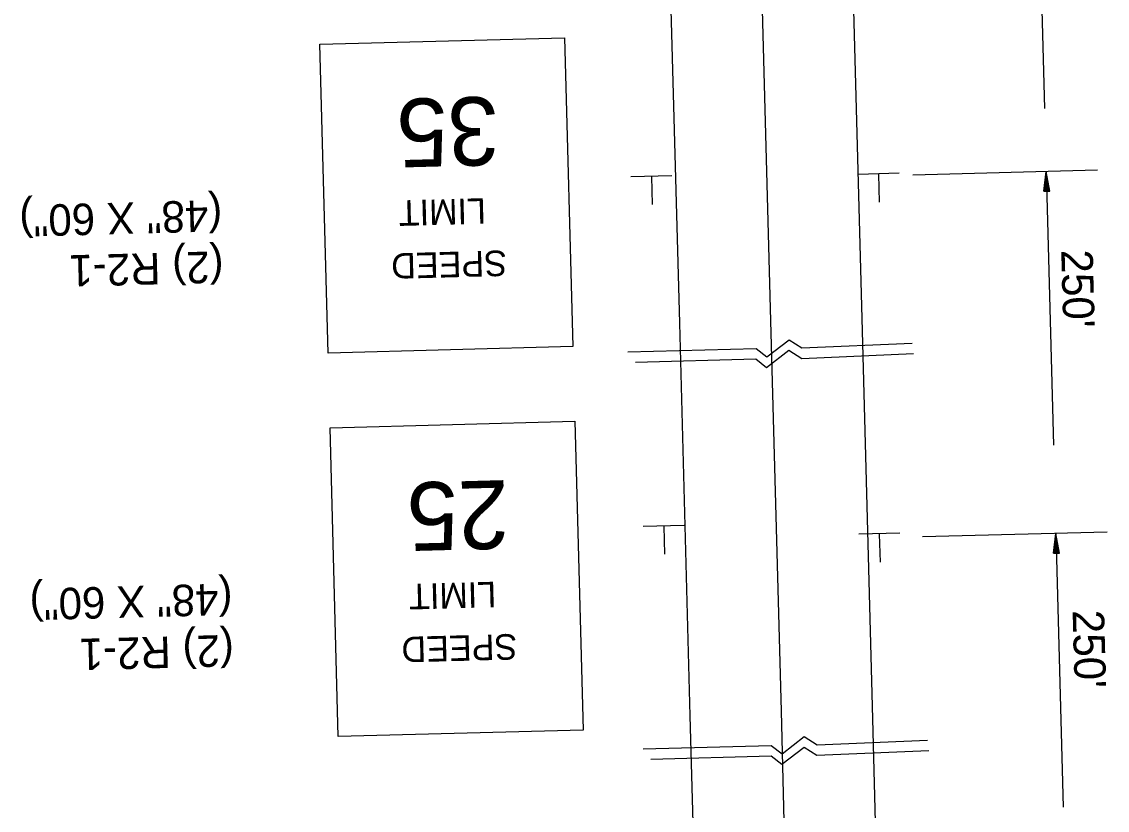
# Model space of a CAD drawing. Extents: x 1929624 to 1932607, y 596315 to 605533.
# Drawn here: x 1930074.1 to 1930285.9, y 598953.1 to 599106.9 of the extents above; entities that cross this region are included whole.
import ezdxf

# ---------------------------------------------------------------- set-up
doc = ezdxf.new("R2010")
doc.units = 0
doc.layers.add('Default', color=7, linetype='Continuous')

msp = doc.modelspace()

# ---------------------------------------------------------------- linework, layer by layer
at = {"layer": 'Default'}
for p, q in [((1930272.25, 599143.34), (1930273.68, 599089.95)), ((1930200.55, 599118.68), (1930202.45, 599048.1)), ((1930218.34, 599119.16), (1930220.23, 599048.58)), ((1930236.12, 599119.64), (1930238.01, 599049.05)), ((1930192.99, 599076.71), (1930200.99, 599076.93)), ((1930196.98, 599076.7), (1930197.12, 599071.24)), ((1930237.32, 599077.21), (1930245.32, 599077.42)), ((1930241.3, 599077.2), (1930241.45, 599071.73)), ((1930284.03, 599077.98), (1930248.01, 599077.01)), ((1930273.54, 599073.86), (1930274.01, 599077.71)), ((1930273.63, 599073.86), (1930274.03, 599077.07)), ((1930273.73, 599073.86), (1930274.05, 599076.41)), ((1930274.01, 599077.71), (1930275.44, 599024.33)), ((1930274.69, 599073.89), (1930274.01, 599077.71)), ((1930274.59, 599073.89), (1930274.03, 599077.07)), ((1930274.5, 599073.88), (1930274.05, 599076.41)), ((1930273.83, 599073.86), (1930274.06, 599075.77)), ((1930273.93, 599073.87), (1930274.08, 599075.12)), ((1930274.02, 599073.87), (1930274.1, 599074.48)), ((1930274.4, 599073.88), (1930274.06, 599075.77)), ((1930274.3, 599073.88), (1930274.08, 599075.12)), ((1930274.2, 599073.87), (1930274.1, 599074.48)), ((1930273.54, 599073.86), (1930274.69, 599073.89)), ((1930238.01, 599049.05), (1930240.04, 598973.42)), ((1930202.45, 599048.1), (1930204.5, 598971.53)), ((1930220.23, 599048.58), (1930222.27, 598972.47)), ((1930195.4, 599008.53), (1930203.4, 599008.75)), ((1930199.38, 599008.52), (1930199.53, 599003.06)), ((1930237.47, 599007.02), (1930245.47, 599007.24)), ((1930241.45, 599007.01), (1930241.6, 599001.55)), ((1930285.92, 599007.39), (1930249.9, 599006.43)), ((1930275.43, 599003.27), (1930275.91, 599007.12)), ((1930275.53, 599003.28), (1930275.92, 599006.48)), ((1930275.91, 599007.12), (1930277.34, 598953.74)), ((1930276.58, 599003.3), (1930275.91, 599007.12)), ((1930276.49, 599003.3), (1930275.92, 599006.48)), ((1930275.63, 599003.28), (1930275.94, 599005.82)), ((1930275.72, 599003.28), (1930275.96, 599005.18)), ((1930275.82, 599003.28), (1930275.97, 599004.53)), ((1930276.39, 599003.3), (1930275.94, 599005.82)), ((1930276.29, 599003.3), (1930275.96, 599005.18)), ((1930276.2, 599003.29), (1930275.97, 599004.53)), ((1930275.43, 599003.27), (1930276.58, 599003.3)), ((1930275.92, 599003.29), (1930275.99, 599003.89)), ((1930276.1, 599003.29), (1930275.99, 599003.89)), ((1930222.27, 598972.47), (1930223.95, 598909.9)), ((1930240.04, 598973.42), (1930241.74, 598910.03)), ((1930204.5, 598971.53), (1930206.16, 598909.77))]:
    msp.add_line(p, q, dxfattribs=at)
for points in [[(1930133.9, 599042.28), (1930132.28, 599102.5), (1930180.06, 599103.78), (1930181.68, 599043.56)], [(1930135.91, 598967.5), (1930134.29, 599027.71), (1930182.07, 599029), (1930183.68, 598968.78)]]:
    msp.add_lwpolyline(points, close=True, dxfattribs=at)
for points in [[(1930247.86, 599044.15), (1930226.36, 599043.25), (1930223.84, 599044.84), (1930219.5, 599041.48), (1930217.41, 599043.13), (1930192.39, 599042.47)], [(1930248.12, 599042.12), (1930226.33, 599041.2), (1930223.81, 599042.79), (1930219.47, 599039.44), (1930217.38, 599041.09), (1930193.89, 599040.46)], [(1930250.83, 598966.76), (1930229.32, 598965.86), (1930226.81, 598967.45), (1930222.47, 598964.1), (1930220.38, 598965.74), (1930195.36, 598965.08)], [(1930251.08, 598964.73), (1930229.29, 598963.81), (1930226.78, 598965.4), (1930222.44, 598962.05), (1930220.34, 598963.7), (1930196.85, 598963.07)]]:
    msp.add_lwpolyline(points, dxfattribs=at)

# ---------------------------------------------------------------- texts
for s, height, rotation, p in [('35', 13.342, 181.5377, (1930167, 599092.33)), ('(48" X 60")', 6.1396, 181.5377, (1930113.2, 599072.17)), ('LIMIT', 4.978, 181.5377, (1930164.64, 599072.51)), ('(2) R2-1', 6.14, 181.5377, (1930113.46, 599062.17)), ('SPEED', 4.978, 181.5377, (1930168.73, 599062.33)), ("250'", 6.14, 271.5377, (1930276.93, 599062.39)), ('25', 13.342, 181.5377, (1930169.01, 599017.54)), ('(48" X 60")', 6.1396, 181.5377, (1930115.2, 598997.39)), ('LIMIT', 4.978, 181.5377, (1930166.65, 598997.72)), ("250'", 6.14, 271.5377, (1930279.15, 598992.13)), ('(2) R2-1', 6.14, 181.5377, (1930115.47, 598987.38)), ('SPEED', 4.978, 181.5377, (1930170.74, 598987.54))]:
    msp.add_text(s, height=height, rotation=rotation, dxfattribs=at).set_placement(p)

doc.saveas('drawing.dxf')
